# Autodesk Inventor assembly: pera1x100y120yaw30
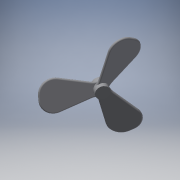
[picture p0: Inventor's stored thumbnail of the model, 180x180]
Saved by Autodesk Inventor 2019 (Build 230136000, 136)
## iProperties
Created: 2020-08
Part Number: pera1x100y120yaw30
Material: 一般
Document SubType Name: Assembly
Designer: kikut
Author: kikut
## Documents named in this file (2)
- F:\openFOAM\bathrobo\bathrobo05\oversetmeshpera1\CAD\pera1x100y120yaw30.iam
- F:\openFOAM\bathrobo\bathrobo05\oversetmeshpera1\CAD\pera01.ipt
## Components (1 placed, 1 different names)
1. pera01:1 — 角度:1, メイト:1, メイト:2, メイト:3
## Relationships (4: Mate 3, Angle 1)
- 角度:1 [Angle]: pera01:1
- メイト:1 [Mate]: pera01:1
- メイト:2 [Mate]: pera01:1
- メイト:3 [Mate]: pera01:1
